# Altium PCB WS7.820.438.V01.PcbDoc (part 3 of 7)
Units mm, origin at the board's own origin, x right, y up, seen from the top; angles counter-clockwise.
Board outline 143.01 x 224 mm, 4 copper layers (Top Layer, G2, S3, Bottom Layer); 863 components, 638 nets, 2623 pads, 4664 vias.
Unrouted connection lines stored in the file: 16.
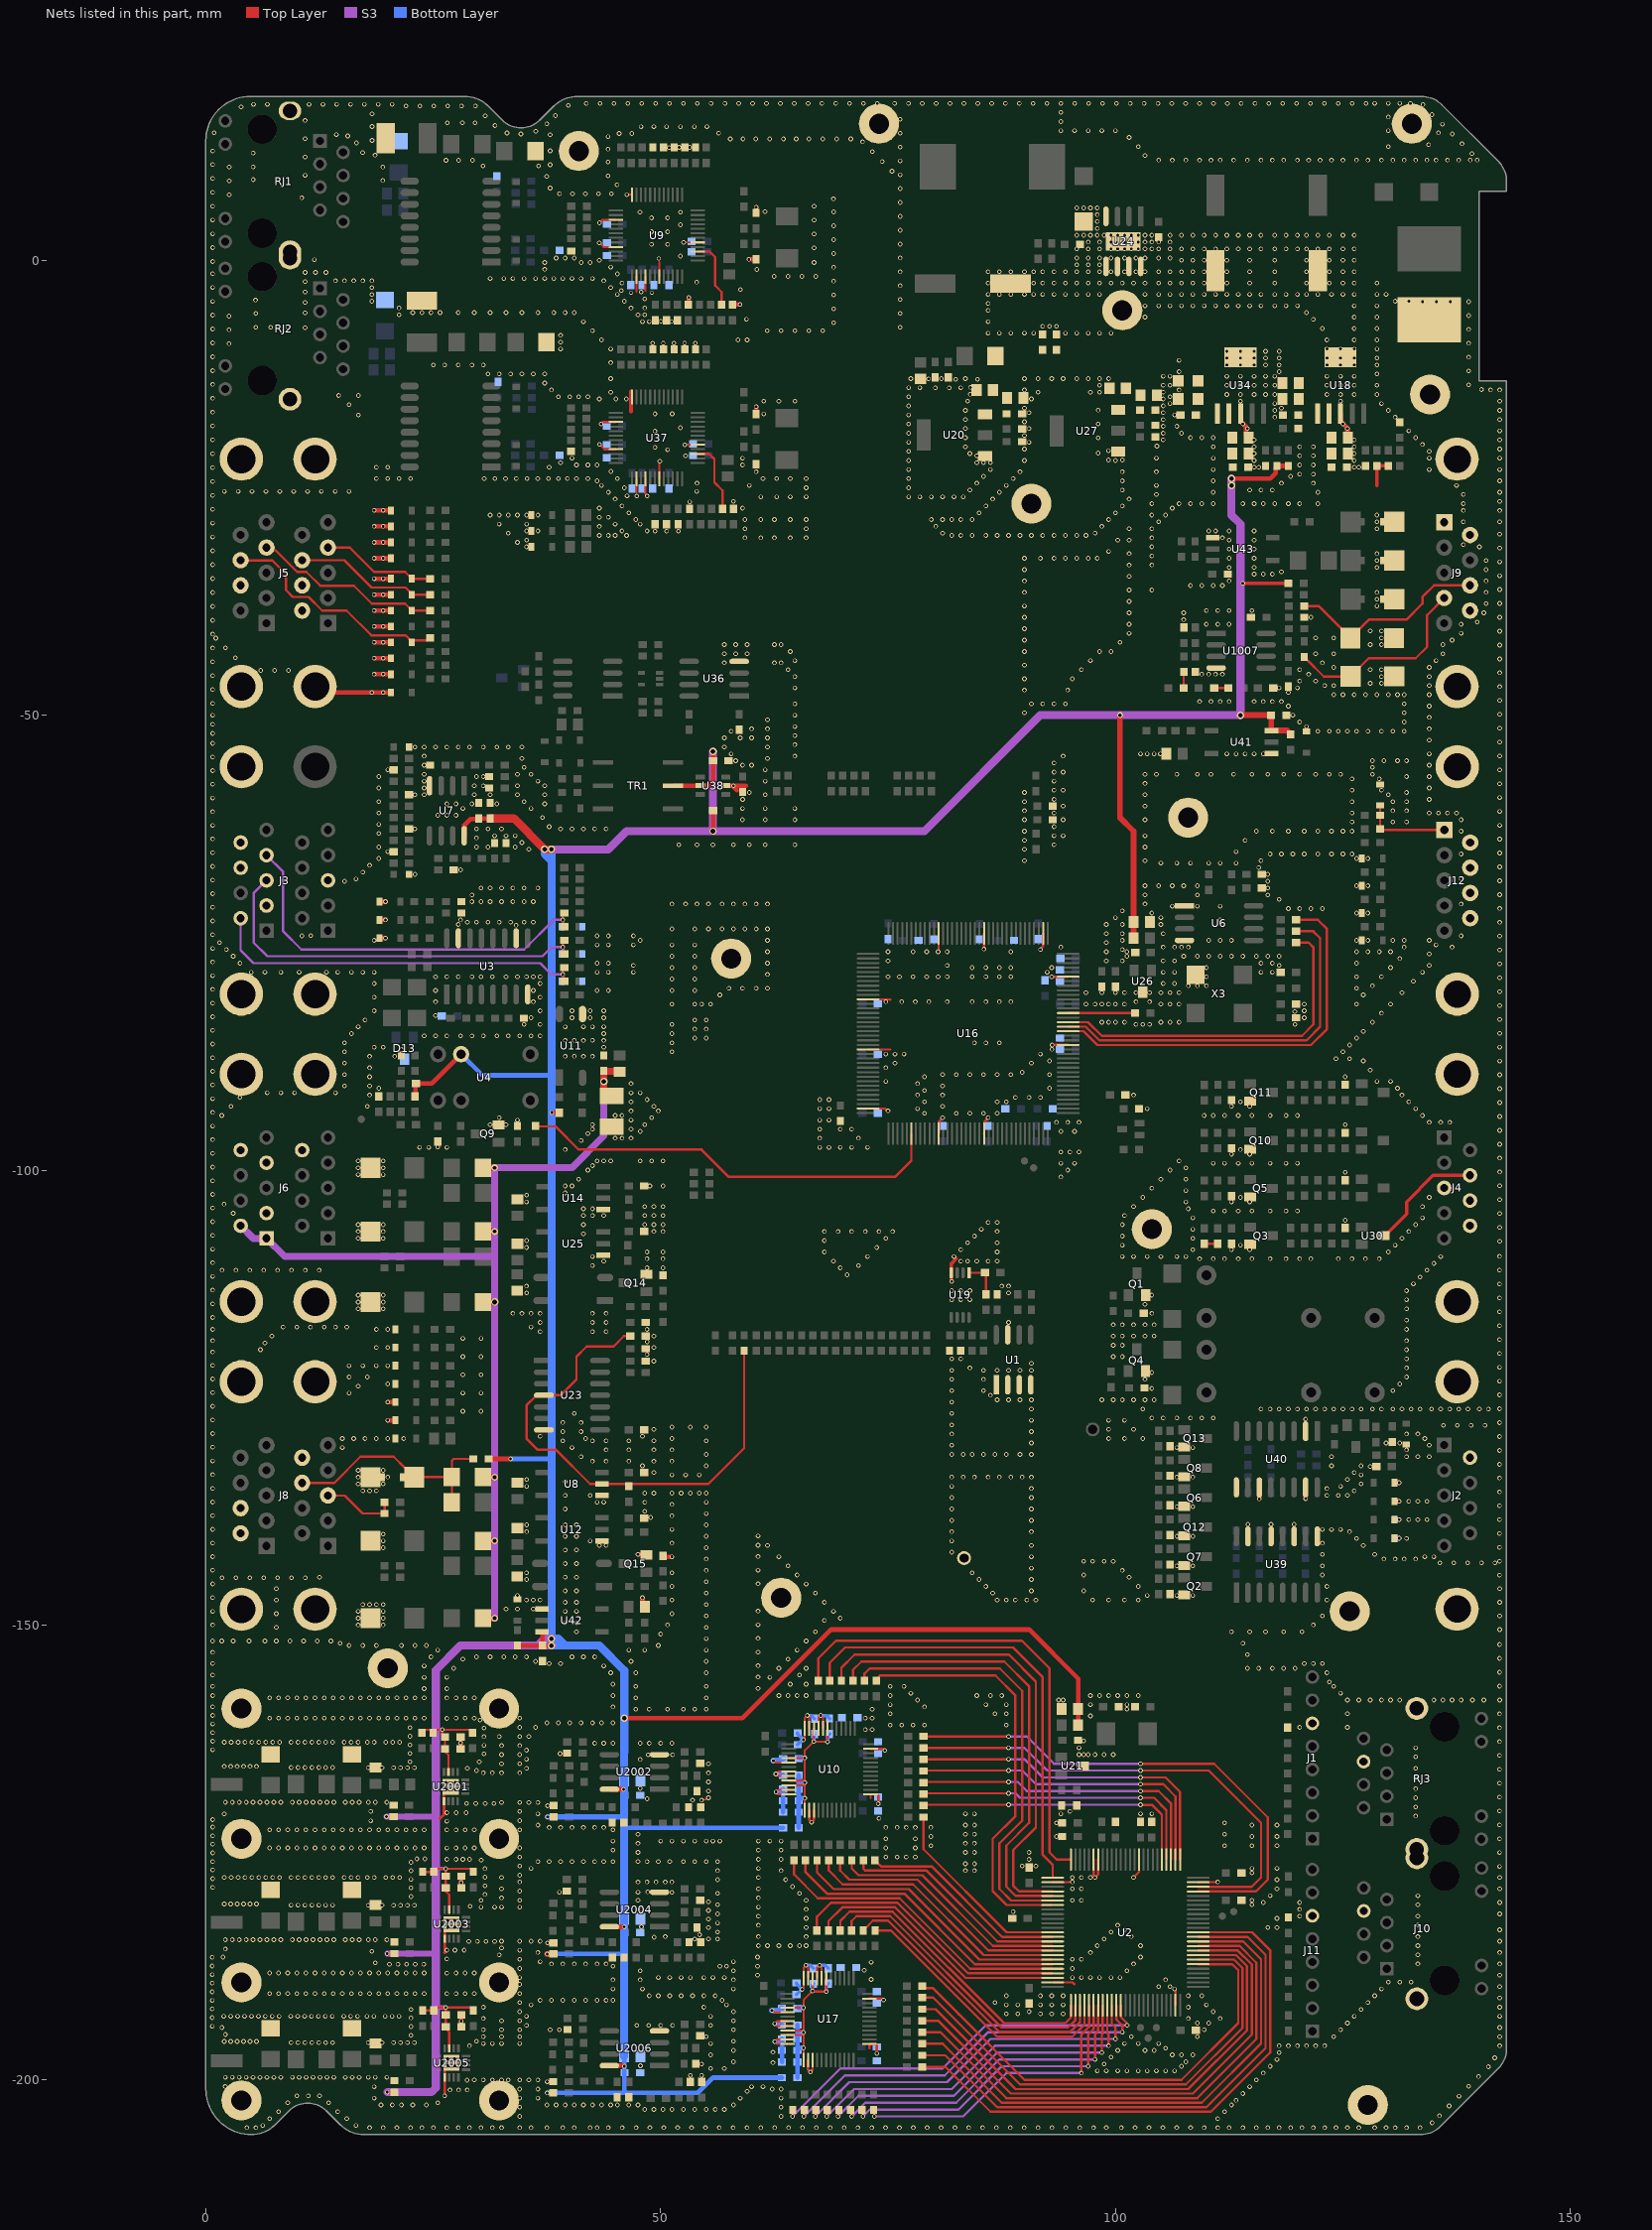
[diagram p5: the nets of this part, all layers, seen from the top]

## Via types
v1: diameter 0.508, hole 0.305, Top Layer to Bottom Layer, tented both sides, 4404 vias
v2: diameter 0.508, hole 0.3, Top Layer to Bottom Layer, tented both sides, 200 vias
v3: diameter 0.813, hole 0.508, Top Layer to Bottom Layer, tented both sides, 31 vias
v4: diameter 0.457, hole 0.305, Top Layer to Bottom Layer, tented both sides, 10 vias
v5: diameter 0.66, hole 0.406, Top Layer to Bottom Layer, tented both sides, 9 vias
v6: diameter 0.762, hole 0.406, Top Layer to Bottom Layer, tented both sides, 6 vias
v7: diameter 0.711, hole 0.406, Top Layer to Bottom Layer, tented both sides, 4 vias

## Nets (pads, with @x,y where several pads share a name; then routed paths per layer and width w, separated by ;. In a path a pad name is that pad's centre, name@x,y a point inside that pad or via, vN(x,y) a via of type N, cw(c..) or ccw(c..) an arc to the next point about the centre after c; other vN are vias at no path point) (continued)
24VIN_SHIDU: C80.2 C81.2 J6.A1 J6.A6 L1.2 R183.2 R189.2 R191.2 R193.2 R201.2 R227.2 | length 111
  Top Layer w0.762: R189.2@30.45,-114.5 v3(31.75,-114.5) ; R201.2@30.45,-106.75 v6(31.75,-106.75) ; R191.2@30.45,-99.75 v6(31.75,-99.75) ; R193.2@30.5,-149.25 v6(31.75,-149.25) ; R183.2@30.5,-140.75 v6(31.75,-140.75) ; R227.2@30.5,-133.75 v6(31.75,-133.75) ; C81.2@43.75,-89.1 C81.2@43.75,-89.136 ; C80.2@44.617,-91.837 44.269,-91.837 43.75,-91.318 v3(43.75,-90.25) C81.2@43.75,-89.136 ; L1.2@45.494,-89.21 45.439,-89.155 43.769,-89.155 C81.2@43.75,-89.136
  S3 w0.762: J6.A6@3.826,-106.118 5.211,-107.503 J6.A1@6.666,-107.503 8.663,-109.5 31.75,-109.5 ; v6(31.75,-149.25) v6(31.75,-140.75) v6(31.75,-133.75) v3(31.75,-114.5) 31.75,-109.5 ; v3(43.75,-90.25) 43.75,-96.25 40.25,-99.75 v6(31.75,-99.75) v6(31.75,-106.75) 31.75,-109.5
28V_SW: R226.1 U16.114 | length 47.3
  Top Layer w0.254: R226.1@36.25,-95.2 38.45,-95.2 41,-97.75 54.5,-97.75 57.5,-100.75 75.75,-100.75 77.551,-98.949 U16.114@77.551,-95.987
+5.5V: C28.2 C30.2 C87.2 C88.2 C90.2 C128.2 C129.2 C130.2 C178.2 C180.2 C181.2 C201.2 C202.2 C203.2 FB12.2 R160.2 U18.1 U20.3 U27.3 U34.1
+5V: C21.2 C22.1 C95.2 C112.2 C116.2 C124.2 C125.2 C175.2 C204.2 C205.2 C207.2 C2001.2 C2002.1 C2003.2 C2004.2 C2005.1 C2006.1 C2007.1 C2015.2 C2016.1 C2017.2 C2018.2 C2019.1 C2020.1 C2021.1 C2029.2 C2030.1 C2031.2 C2032.2 C2033.1 C2034.1 C2035.1 FB13.2 FB26.2 L2.1 L12.1 R15.1 R22.1 R46.2 R53.2 R58.1 R144.2 R159.2 R303.1 R352.1 R2005.2 R2015.1 R2020.2 R2035.1 R2041.2 R2054.1 TR1.2 U4.9 U7.8 U34.2 U38.5 U41.6 U42.6 U2001.15 U2002.8 U2003.15 U2004.8 U2005.15 U2006.8 | length 605.8
  Top Layer w0.254: v1(19.858,-171.072) R2015.1@20.634,-171.072 ; v1(19.946,-201.35) R2054.1@20.721,-201.35 ; v1(19.946,-186.11) R2035.1@20.721,-186.11 ; C2007.1@23.744,-161.84 24.063,-161.522 24.989,-161.522 24.994,-161.517 25.983,-161.517 v1(26,-161.5) ; C2035.1@23.832,-192.372 C2032.2@25.077,-192.372 25.42,-192.028 v1(26.372,-192.028) 29.051,-192.028 C2031.2@29.395,-192.372 ; C2021.1@23.832,-177.132 C2018.2@25.077,-177.132 25.42,-176.788 v1(26.372,-176.788) 29.051,-176.788 C2017.2@29.395,-177.132 ; v1@26.386,-192.042 C2029.2@26.386,-192.841 C2030.1@26.386,-194.145 26.386,-194.386 26.757,-194.757 U2005.15@26.757,-196.524 ; v1@26.386,-176.802 C2015.2@26.386,-177.601 C2016.1@26.386,-178.905 26.386,-179.273 26.757,-179.644 U2003.15@26.757,-181.284 ; U2001.15@26.624,-166.124 U2001.15@26.669,-166.169 26.669,-164.277 26.298,-163.906 C2002.1@26.298,-163.613 C2001.2@26.298,-162.309 26.273,-162.309 26,-162.036 v1(26,-161.5) ; C2003.2@29.307,-161.84 29.307,-161.79 29.034,-161.517 26.017,-161.517 v1(26,-161.5)
  Top Layer w0.381: v1(114,-35.5) R352.1@118.95,-35.5
  Top Layer w0.508: R144.2@23,-92 23.05,-91.95 23.05,-90.55 R53.2@23.1,-90.5 ; R53.2@23,-90.5 R53.2@23.1,-90.5 ; U4.9@28.065,-87.261 24.826,-90.5 R53.2@23.1,-90.5 ; U7.8@28.405,-63.25 28.423,-63.232 28.423,-62.077 29.1,-61.4 C21.2@30,-61.4 ; C21.2@30,-61.35 31.15,-61.35 C22.1@31.25,-61.25 ; R46.2@31.1,-131.75 v1(33.5,-131.75) ; R58.1@34.258,-152.258 C125.2@37,-152.258 ; U42.6@36.95,-150.77 36.954,-150.77 37,-150.816 C125.2@37,-152.258 ; v3(38,-152.258) C125.2@37,-152.258 ; v1(38.036,-93.687) R22.1@38.871,-93.687 R22.1@38.859,-93.675 ; U2006.8@44.367,-198.429 45.929,-198.429 v1(46,-198.5) ; U2004.8@44.367,-183.169 44.494,-183.169 v1@45.91,-183.169 ; U2002.8@44.367,-168.059 v1(45.91,-168.059) ; v3(46,-160.25) 59,-160.25 68.75,-150.5 90.5,-150.5 95.9,-155.9 C116.2@95.9,-158.75 ; TR1.2@51.357,-57.75 U38.5@54.357,-57.75 55.25,-57.75 55.757,-57.243 C112.2@55.757,-55 55.754,-54.996 55.754,-54.004 v3(55.75,-54) ; v3(55.75,-62.75) 55.754,-62.746 55.754,-60.503 R303.1@55.757,-60.5 ; L2.1@95.9,-161 C116.2@95.9,-159.25 ; v3(112.75,-24) 117,-24 117.619,-23.381 117.619,-22.731 R159.2@117.75,-22.6 C207.2@119,-22.6
  Top Layer w0.635: v1(37.526,-186.16) R2020.2@38.219,-186.16 ; v5(100.5,-50) 100.5,-61.25 102,-62.75 C175.2@102,-72.75 L12.1@102,-74.5 ; v3(113.75,-50) C124.2@117.1,-50 117.125,-50.025 117.125,-51.672 117.142,-51.69 U41.6@117.15,-51.69 118.88,-51.69 119.25,-52.06 R15.1@119.25,-52.11
  Top Layer w0.889: C22.1@31.25,-61.35 33.85,-61.35 v3(37.25,-64.75) v3(38,-64.75)
  S3 w0.254: 25.28,-161.517 25.983,-161.517 v1(26,-161.5)
  S3 w0.381: 25.28,-176.788 v1(26.372,-176.788)
  S3 w0.508: 25.381,-192.028 v1(26.372,-192.028)
  S3 w0.635: v1(19.858,-171.072) 25.192,-171.072 ; v1(19.946,-186.11) 25.242,-186.11
  S3 w0.889: v1(19.946,-201.35) 24.797,-201.35 25.28,-200.867 25.28,-176.788 25.28,-161.517 25.28,-154.97 28,-152.25 36.5,-152.25 37.25,-151.5 v3(38,-151.5) ; 36.5,-152.258 v3(38,-152.258) ; v3(37.25,-64.75) 44.25,-64.75 46.25,-62.75 v3(55.75,-62.75) ; v3(55.75,-54) v3(55.75,-62.75) ; v3(112.75,-24) v3(112.75,-24.75) 112.75,-28 113.75,-29 v3(113.75,-50) v5(100.5,-50) 91.75,-50 79,-62.75 v3(55.75,-62.75)
  Bottom Layer w0.508: U4.9@28.065,-87.261 30.39,-89.585 38,-89.585 ; v1(33.5,-131.75) 38,-131.75 ; v1(37.52,-201.434) 46.042,-201.434 ; v1(37.526,-186.16) 45.899,-186.16 ; C2034.1@45.992,-197.421 46,-197.429 v1(46,-198.5) 46,-201.392 46.042,-201.434 ; 45.992,-172.25 46.039,-172.296 FB26.2@63.472,-172.296 ; FB13.2@63.332,-199.746 55.754,-199.746 54.066,-201.434 46.042,-201.434
  Bottom Layer w0.635: v1(37.571,-171.089) 45.903,-171.089 45.992,-171
  Bottom Layer w0.889: v1@38,-93.723 38,-131.75 v3(38,-151.5) ; v1@38,-93.651 38,-89.585 38,-66.5 38,-66 ; 39.5,-152.25 38.75,-151.5 v3(38,-151.5) ; C2034.1@45.992,-197.421 C2020.1@45.992,-182.288 45.992,-172.25 45.992,-171 C2006.1@45.992,-167.068 45.992,-163.935 46,-163.927 v3(46,-160.25) 46,-155 43.258,-152.258 v3(38,-152.258) v3(38,-151.5) ; 38,-66 37.25,-65.25 v3(37.25,-64.75) v3(38,-64.75) 38,-66
  other v1: 45.992,-183.177
+5V_1: C131.2 C132.2 C133.2 C134.2 J9.1 R108.2 U18.2 | length 3.4
  Top Layer w0.381: 128.75,-24.75 C131.2@128.75,-22.6 R108.2@130,-22.6
+5VA1: C73.2 C74.2 C75.2 C76.2 C77.2 C78.2 C79.2 FB13.1 U17.4 U17.9 U17.10 U17.13 U17.43 U17.46 | length 27.4
  Top Layer w0.229: U17.10@63.954,-195.059 65.702,-195.059 ; U17.9@63.954,-194.559 v1@65.699,-194.559 ; U17.4@63.954,-192.059 v1@65.699,-192.059 ; U17.13@65.704,-197.809 v1@65.704,-196.51 ; v1(65.704,-196.484) v1(65.704,-194.782) v1(65.704,-192.065) 65.704,-191.231 v1(66.692,-190.244) 66.692,-188.822 U17.46@66.704,-188.809 ; v1@66.692,-190.293 v1@68.203,-190.293 ; v1(68.204,-190.292) U17.43@68.204,-188.809
  Bottom Layer w0.381: v1(66.692,-190.244) 66.692,-189.512 C77.2@66.775,-189.429 ; v1(68.204,-190.292) 68.204,-189.65 C78.2@68.426,-189.429
  Bottom Layer w0.508: FB13.1@65.032,-199.746 C79.2@65.032,-198.032 C76.2@65.032,-196.762 ; C74.2@65.032,-193.968 65.032,-194.782 ; C73.2@65.032,-192.003 65.094,-192.065 v1(65.704,-192.065) ; v1(65.704,-196.484) 65.31,-196.484 C76.2@65.032,-196.762 ; v1(65.704,-194.782) 65.032,-194.782 ; C76.2@65.032,-196.762 C75.2@65.032,-195.492 65.032,-194.782
+5VA2: C91.2 C92.2 C96.2 C97.2 C98.2 C99.2 C100.2 FB26.1 U10.4 U10.9 U10.10 U10.13 U10.43 U10.46 | length 27.4
  Top Layer w0.229: U10.10@64.094,-167.609 65.842,-167.609 ; U10.9@64.094,-167.109 v1@65.839,-167.109 ; U10.4@64.094,-164.609 v1@65.839,-164.609 ; U10.13@65.844,-170.359 v1@65.844,-169.06 ; v1(65.844,-169.034) v1(65.844,-167.332) v1(65.844,-164.615) 65.844,-163.781 v1(66.832,-162.794) 66.832,-161.372 U10.46@66.844,-161.359 ; v1@66.832,-162.843 v1@68.343,-162.843 ; v1(68.344,-162.842) U10.43@68.344,-161.359
  Bottom Layer w0.381: v1(66.832,-162.794) 66.832,-162.062 C98.2@66.915,-161.979 ; v1(68.344,-162.842) 68.344,-162.2 C99.2@68.566,-161.979
  Bottom Layer w0.508: FB26.1@65.172,-172.296 C100.2@65.172,-170.582 C97.2@65.172,-169.312 ; C92.2@65.172,-166.518 65.172,-167.332 ; C91.2@65.172,-164.553 65.234,-164.615 v1(65.844,-164.615) ; v1(65.844,-169.034) 65.451,-169.034 C97.2@65.172,-169.312 ; v1(65.844,-167.332) 65.172,-167.332 ; C97.2@65.172,-169.312 C96.2@65.172,-168.042 65.172,-167.332
ACTLED: R73.2 U9.27 | length 7.7
  Top Layer w0.254: U9.27@54.092,0.963 55.374,0.963 56,0.337 56,-2.792 56.692,-3.484 R73.2@56.692,-4.895
ACTLED2: R275.2 U37.27 | length 7.9
  Top Layer w0.254: U37.27@54.092,-21.275 55.337,-21.275 55.899,-21.837 55.899,-24.399 56.802,-25.302 56.802,-26.843 R275.2@56.802,-27.311
AD1_BUSY: R117.2 U2.54 | length 30.6
  Top Layer w0.254: R117.2@73.576,-183.579 75.329,-183.579 87,-195.25 95.25,-195.25 96.596,-193.904 U2.54@96.596,-191.781 ; R117.2@73.849,-183.256 R117.2@73.877,-183.256
AD1_BYTE: R112.2 U2.52 | length 32.9
  Top Layer w0.254: R112.2@70.994,-183.569 70.994,-182.54 71.534,-182 75.25,-182 87.5,-194.25 94.772,-194.25 95.596,-193.426 U2.52@95.596,-191.781
AD1_CONVST: R99.2 U2.51 | length 33.5
  Top Layer w0.254: R99.2@69.724,-183.569 69.75,-183.544 69.75,-182.514 70.764,-181.5 75.5,-181.5 87.75,-193.75 94.5,-193.75 95.096,-193.154 U2.51@95.096,-191.781
AD1_CS: R48.2 U2.47 | length 31.3
  Top Layer w0.254: R48.2@67.184,-183.569 67.184,-182.066 68.719,-180.531 76.031,-180.531 83.781,-188.281 U2.47@93.096,-188.281
AD1_D0: R118.2 U2.81 | length 52.1
  Top Layer w0.254: R118.2@78.755,-189.682 78.966,-189.894 79.894,-189.894 82.784,-192.784 90,-200 107.25,-200 113.5,-193.75 113.5,-187.95 112.832,-187.281 U2.81@109.096,-187.281
AD1_D1: R122.2 U2.82 | length 53.6
  Top Layer w0.254: R122.2@78.755,-190.952 79.952,-190.952 89.5,-200.5 107.75,-200.5 113.967,-194.283 113.967,-187.709 113.039,-186.781 U2.82@109.096,-186.781
AD1_D2: R124.2 U2.83 | length 54.9
  Top Layer w0.254: R124.2@78.755,-192.222 80.222,-192.222 89,-201 108,-201 114.467,-194.533 114.467,-187.502 113.246,-186.281 U2.83@109.096,-186.281
AD1_D3: R125.2 U2.84 | length 56.5
  Top Layer w0.254: R125.2@78.755,-193.492 80.492,-193.492 88.5,-201.5 108.5,-201.5 115,-195 115,-187.328 113.453,-185.781 U2.84@109.096,-185.781
AD1_D4: R126.2 U2.85 | length 58
  Top Layer w0.254: R126.2@78.755,-194.762 80.762,-194.762 88,-202 109,-202 115.5,-195.5 115.5,-187.121 113.66,-185.281 U2.85@109.096,-185.281
AD1_D5: R130.2 U2.86 | length 59.6
  Top Layer w0.254: R130.2@78.755,-196.032 81.032,-196.032 87.5,-202.5 109.5,-202.5 116,-196 116,-186.75 114.031,-184.781 U2.86@109.096,-184.781
AD1_D6: R131.2 U2.87 | length 61.3
  Top Layer w0.254: R131.2@78.755,-197.302 81.302,-197.302 87,-203 110,-203 116.5,-196.5 116.5,-186.25 114.531,-184.281 U2.87@109.096,-184.281
AD1_D7: R132.2 U2.88 | length 62.9
  Top Layer w0.254: R132.2@78.755,-198.572 81.322,-198.572 86.25,-203.5 110.5,-203.5 117,-197 117,-185.75 115.031,-183.781 U2.88@109.096,-183.781
AD1_D8: R140.1 U2.55 | length 32.5
  Top Layer w0.254: v1(96.25,-199.25) 96.25,-195 97.096,-194.154 U2.55@97.096,-191.781
  S3 w0.254: v1(73.5,-204) 83.25,-204 88,-199.25 v1(96.25,-199.25)
AD1_D9: R139.1 U2.56 | length 34
  Top Layer w0.254: v1(97,-198.5) 97,-195 97.596,-194.404 U2.56@97.596,-191.781
  S3 w0.254: v1(72.25,-204) 72.976,-203.274 82.726,-203.274 87.5,-198.5 v1(97,-198.5)
AD1_D10: R138.1 U2.57 | length 35.5
  Top Layer w0.254: v1(97.75,-197.75) 97.75,-195 98.096,-194.654 U2.57@98.096,-191.781
  S3 w0.254: v1(71,-204) 72.5,-202.5 82.5,-202.5 87.25,-197.75 v1(97.75,-197.75)
AD1_D11: R137.1 U2.58 | length 37.2
  Top Layer w0.254: v1(98.5,-197) 98.5,-195 98.596,-194.904 U2.58@98.596,-191.781
  S3 w0.254: v1(69.5,-204) 71.75,-201.75 82.25,-201.75 87,-197 v1(98.5,-197)
AD1_D12: R136.1 U2.59 | length 38.7
  Top Layer w0.254: U2.59@99.096,-191.781 99.096,-194.846 99.25,-195 v1(99.25,-196.25)
  S3 w0.254: v1(68.25,-204) 71.25,-201 82,-201 86.75,-196.25 v1(99.25,-196.25)
AD1_D13: R135.1 U2.60 | length 40.4
  Top Layer w0.254: U2.60@99.596,-191.781 99.596,-193.846 100,-194.25 v1(100,-195.5)
  S3 w0.254: v1(67,-204) 70.75,-200.25 81.5,-200.25 86.25,-195.5 v1(100,-195.5)
AD1_D14: R134.1 U2.61 | length 42.1
  Top Layer w0.254: U2.61@100.096,-191.781 100.096,-193.346 100.75,-194 v1(100.75,-194.75)
  S3 w0.254: v1(65.75,-204) 70.25,-199.5 81.25,-199.5 86,-194.75 v1(100.75,-194.75)
AD1_D15: R133.1 U2.62 | length 43.4
  Top Layer w0.254: U2.62@100.596,-191.781 100.596,-193.096 101.235,-193.735 101.235,-193.951 v1(101.283,-194)
  S3 w0.254: v1(64.5,-204) 69.75,-198.75 81,-198.75 85.75,-194 v1(101.283,-194)
AD1_RD: R60.2 U2.48 | length 29.5
  Top Layer w0.254: R60.2@68.454,-183.569 68.454,-182.546 69.969,-181.031 75.781,-181.031 83.531,-188.781 U2.48@93.096,-188.781
AD1_RESET: R114.2 U2.53 | length 31.7
  Top Layer w0.254: R114.2@72.264,-183.569 72.264,-183.519 72.537,-183.246 72.587,-183.246 73.334,-182.5 75,-182.5 87.25,-194.75 95,-194.75 96.096,-193.654 U2.53@96.096,-191.781
AD2_BUSY: R237.2 U2.32 | length 46.2
  Top Layer w0.254: R237.2@73.639,-156.007 74.104,-155.542 86.792,-155.542 89,-157.75 89,-171 86.5,-173.5 86.5,-179.25 88.031,-180.781 U2.32@93.096,-180.781
AD2_BYTE: R235.2 U2.30 | length 50.6
  Top Layer w0.254: R235.2@71.134,-156.119 71.134,-154.956 72.072,-154.018 87.792,-154.018 90.5,-156.726 90.5,-171.75 88,-174.25 88,-178.75 89.031,-179.781 U2.30@93.096,-179.781
AD2_CONVST: R234.2 U2.29 | length 52.7
  Top Layer w0.254: R234.2@69.864,-156.119 69.864,-154.702 71.309,-153.257 88.292,-153.257 91.25,-156.215 91.25,-172.25 88.75,-174.75 88.75,-178.633 89.399,-179.281 U2.29@93.096,-179.281
AD2_CS: R232.2 U2.25 | length 52.8
  Top Layer w0.254: R232.2@67.324,-156.119 67.324,-153.676 69.274,-151.726 89.726,-151.726 92.75,-154.75 92.75,-175 93.531,-175.781 U2.25@95.096,-175.781
AD2_D0: R238.2 U2.97 | length 56.6
  Top Layer w0.254: R238.2@78.895,-162.232 78.913,-162.25 v1(88.25,-162.25) ; v1(102.75,-165.25) 110.85,-165.25 116.75,-171.15 116.75,-178 115.469,-179.281 U2.97@109.096,-179.281
  S3 w0.254: v1(88.25,-162.25) 90.25,-162.25 93.25,-165.25 v1(102.75,-165.25)
AD2_D1: R239.2 U2.98 | length 53.9
  Top Layer w0.254: R239.2@78.896,-163.5 v1(88.25,-163.5) ; v1(102.75,-166) 110.25,-166 116,-171.75 116,-175.25 116,-177.75 114.967,-178.783 U2.98@109.096,-178.781 U2.98@109.096,-178.781
  S3 w0.254: v1(88.25,-163.5) 90,-163.5 92.5,-166 v1(102.75,-166)
AD2_D2: R240.2 U2.1 | length 37.1
  Top Layer w0.254: R240.2@78.895,-164.772 78.916,-164.75 v1(88.25,-164.75) ; v1(102.75,-166.75) 105.5,-166.75 107.096,-168.346 U2.1@107.096,-175.781
  S3 w0.254: v1(88.25,-164.75) 90,-164.75 92,-166.75 v1(102.75,-166.75)
AD2_D3: R241.2 U2.2 | length 35.8
  Top Layer w0.254: R241.2@78.895,-166.042 78.936,-166 v1(88.25,-166) ; v1(102.75,-167.5) 105.25,-167.5 106.596,-168.846 U2.2@106.596,-175.781
  S3 w0.254: v1(88.25,-166) 89.75,-166 91.25,-167.5 v1(102.75,-167.5)
AD2_D4: R242.2 U2.3 | length 34.4
  Top Layer w0.254: R242.2@78.895,-167.312 78.956,-167.25 v1(88.25,-167.25) ; v1(102.75,-168.25) 104.75,-168.25 106.096,-169.596 U2.3@106.096,-175.781
  S3 w0.254: v1(88.25,-167.25) 89.25,-167.25 90.25,-168.25 v1(102.75,-168.25)
AD2_D5: R243.2 U2.4 | length 32.9
  Top Layer w0.254: R243.2@78.895,-168.582 78.976,-168.5 v1(88.25,-168.5) ; v1(102.75,-169) 104.25,-169 105.596,-170.346 U2.4@105.596,-175.781
  S3 w0.254: v1(88.25,-168.5) 89,-168.5 89.5,-169 v1(102.75,-169)
AD2_D6: R244.2 U2.5 | length 31.6
  Top Layer w0.254: R244.2@78.895,-169.852 78.996,-169.75 v1(88.25,-169.75) ; v1(102.75,-169.75) 102.799,-169.799 104.049,-169.799 105.096,-170.846 U2.5@105.096,-175.781
  S3 w0.254: v1(88.25,-169.75) v1(102.75,-169.75)
AD2_D7: R245.2 U2.38 | length 21.5
  Top Layer w0.254: R245.2@78.895,-171.122 78.895,-174.645 88.031,-183.781 U2.38@93.096,-183.781
AD2_D8: R253.1 U2.39 | length 23.1
  Top Layer w0.254: R253.1@73.547,-175.853 73.547,-175.903 73.82,-176.176 73.87,-176.176 74.226,-176.531 79.781,-176.531 87.531,-184.281 U2.39@93.096,-184.281
AD2_D9: R252.1 U2.40 | length 25.1
  Top Layer w0.254: R252.1@72.277,-175.853 72.286,-175.861 72.286,-176.786 72.5,-177 79.25,-177 87.031,-184.781 U2.40@93.096,-184.781
AD2_D10: R251.1 U2.41 | length 26.5
  Top Layer w0.254: R251.1@71.007,-175.853 71.007,-176.757 71.75,-177.5 78.75,-177.5 86.531,-185.281 U2.41@93.096,-185.281
AD2_D11: R250.1 U2.42 | length 28.1
  Top Layer w0.254: R250.1@69.737,-175.853 69.737,-176.987 70.75,-178 78.25,-178 86.031,-185.781 U2.42@93.096,-185.781
AD2_D12: R249.1 U2.43 | length 29.6
  Top Layer w0.254: R249.1@68.467,-175.853 68.467,-176.967 70,-178.5 77.75,-178.5 85.531,-186.281 U2.43@93.096,-186.281
AD2_D13: R248.1 U2.44 | length 31.2
  Top Layer w0.254: R248.1@67.197,-175.853 67.197,-177.197 69.031,-179.031 77.281,-179.031 85.031,-186.781 U2.44@93.096,-186.781
AD2_D14: R247.1 U2.45 | length 32.7
  Top Layer w0.254: R247.1@65.927,-175.853 65.927,-177.177 68.281,-179.531 76.781,-179.531 84.531,-187.281 U2.45@93.096,-187.281
AD2_D15: R246.1 U2.46 | length 34.3
  Top Layer w0.254: R246.1@64.657,-175.853 64.657,-177.407 67.281,-180.031 76.281,-180.031 84.031,-187.781 U2.46@93.096,-187.781
AD2_RD: R233.2 U2.26 | length 49.9
  Top Layer w0.254: R233.2@68.594,-156.119 68.594,-154.156 70.274,-152.476 88.726,-152.476 92,-155.75 92,-175.25 93.096,-176.346 U2.26@93.096,-177.781
AD2_RESET: R236.2 U2.31 | length 48.5
  Top Layer w0.254: R236.2@72.404,-156.119 72.404,-155.346 72.97,-154.78 87.292,-154.78 89.75,-157.238 89.75,-171.5 87.25,-174 87.25,-179 88.531,-180.281 U2.31@93.096,-180.281
AGND1: C52.2 C53.2 C73.1 C74.1 C75.1 C76.1 C77.1 C78.1 C79.1 FB15.2 U17.5 U17.7 U17.8 U17.11 U17.12 U17.14 U17.15 U17.44 U17.45 U17.47 U17.48 | length 27.4
  Top Layer w0.229: v1(62.242,-192.369) 62.432,-192.559 U17.5@63.954,-192.559 ; U17.12@63.954,-196.059 62.808,-196.059 v1(62.547,-195.798) 62.786,-195.559 U17.11@63.954,-195.559 ; U17.8@63.954,-194.059 62.764,-194.059 v1(62.522,-193.817) 62.78,-193.559 U17.7@63.954,-193.559 ; v1@65.704,-189.897 U17.48@65.704,-188.809 65.704,-187.663 v1(65.976,-187.391) 66.204,-187.619 U17.47@66.204,-188.809 ; U17.45@67.204,-188.809 67.204,-187.661 v1(67.475,-187.391) 67.704,-187.621 U17.44@67.704,-188.809
  Top Layer w0.254: U17.14@66.204,-197.809 66.204,-198.872 v1(66.459,-199.126) 66.704,-198.88 U17.15@66.704,-197.809
  Bottom Layer w0.381: C53.2@64.922,-190.606 65.472,-190.056 v1(65.545,-190.056) ; C52.2@64.922,-189.336 64.922,-189.433 v1(65.545,-190.056) ; v1@65.545,-189.959 v1(65.545,-190.056) ; v1(65.976,-187.391) 66.437,-187.391 C77.1@66.775,-187.729 ; v1(67.475,-187.391) 68.088,-187.391 C78.1@68.426,-187.729
  Bottom Layer w0.508: v1(62.522,-193.817) 63.181,-193.817 C74.1@63.332,-193.968 ; v1(62.547,-195.798) 63.026,-195.798 C75.1@63.332,-195.492 C76.1@63.332,-196.762 C79.1@63.332,-198.032
  Bottom Layer w0.635: v1(62.242,-192.369) 63.093,-192.369 C73.1@63.332,-192.13
  other v1: 62.344,-198.105 62.344,-196.962
AGND2: C63.2 C64.2 C91.1 C92.1 C96.1 C97.1 C98.1 C99.1 C100.1 FB28.2 U10.5 U10.7 U10.8 U10.11 U10.12 U10.14 U10.15 U10.44 U10.45 U10.47 U10.48 | length 27.4
  Top Layer w0.229: v1(62.382,-164.919) 62.572,-165.109 U10.5@64.094,-165.109 ; U10.12@64.094,-168.609 62.948,-168.609 v1(62.687,-168.348) 62.926,-168.109 U10.11@64.094,-168.109 ; U10.8@64.094,-166.609 62.904,-166.609 v1(62.662,-166.367) 62.92,-166.109 U10.7@64.094,-166.109 ; v1@65.844,-162.447 U10.48@65.844,-161.359 65.844,-160.213 v1(66.116,-159.941) 66.344,-160.169 U10.47@66.344,-161.359 ; U10.45@67.344,-161.359 67.344,-160.211 v1(67.615,-159.941) 67.844,-160.171 U10.44@67.844,-161.359
  Top Layer w0.254: U10.14@66.344,-170.359 66.344,-171.422 v1(66.599,-171.676) 66.844,-171.43 U10.15@66.844,-170.359
  Bottom Layer w0.381: C64.2@65.062,-163.156 65.612,-162.606 v1(65.685,-162.606) ; C63.2@65.062,-161.886 65.062,-161.983 v1(65.685,-162.606) ; v1@65.685,-162.509 v1(65.685,-162.606) ; v1(66.116,-159.941) 66.577,-159.941 C98.1@66.915,-160.279 ; v1(67.615,-159.941) 68.228,-159.941 C99.1@68.566,-160.279
  Bottom Layer w0.508: v1(62.662,-166.367) 63.321,-166.367 C92.1@63.472,-166.518 ; v1(62.687,-168.348) 63.166,-168.348 C96.1@63.472,-168.042 C97.1@63.472,-169.312 C100.1@63.472,-170.582
  Bottom Layer w0.635: v1(62.382,-164.919) 63.233,-164.919 C91.1@63.472,-164.68
BAP70Q_Vctrl_1: D66.2 J9.4 R351.2 | length 21.9
  Top Layer w0.254: R351.2@120.75,-43.6 120.75,-43.65 121.023,-43.923 121.073,-43.923 122.9,-45.75 D66.2@125.85,-45.75 127.85,-43.75 133,-43.75 134.25,-42.5 134.25,-39.009 J9.4@136.139,-37.121
BAP70Q_Vctrl_2: D67.2 J9.8 R350.2 | length 22.6
  Top Layer w0.254: R350.2@120.75,-38 122.33,-38 125.815,-41.485 D67.2@125.815,-41.535 127.85,-39.5 132,-39.5 133.75,-37.75 133.75,-37 135.014,-35.736 J9.8@138.979,-35.736
BD_TEMP: R172.1 R209.2 U19.1 | length 4.5
  Top Layer w0.254: U19.1@83.899,-111.292 85.858,-111.292 85.9,-111.25 R209.2@86,-111.35 ; R172.1@85.75,-113.65 R209.2@85.75,-111.35
BD_TEMP_HCQ: D35.1 J3.A6 R121.2 R127.2 | length 42.5
  Top Layer w0.254: R127.2@39.4,-79.25 39.25,-79.1 v1(39.25,-78.5) 39.25,-77.9 R121.2@39.4,-77.75
  S3 w0.254: J3.A6@3.826,-72.312 3.826,-75.826 5.25,-77.25 36.75,-77.25 38,-78.5 v1(39.25,-78.5)
  Bottom Layer w0.254: D35.1@39.25,-79.327 v1(39.25,-78.5)
BD_TEMP_JG1: D36.1 J3.A3 R120.2 R128.2 | length 44.8
  Top Layer w0.254: R128.2@39.4,-76.25 39.25,-76.1 v1(39.25,-75.5) 39.25,-74.9 R120.2@39.4,-74.75
  S3 w0.254: J3.A3@6.666,-68.157 5.25,-69.573 5.25,-75 6.75,-76.5 37,-76.5 38,-75.5 v1(39.25,-75.5)
  Bottom Layer w0.254: D36.1@39.25,-76.25 v1(39.25,-75.5)
BD_TEMP_JG2: D37.1 J3.A4 R17.2 R129.2 | length 44.4
  Top Layer w0.254: R129.2@39.4,-73.25 39.25,-73.1 v1(39.25,-72.5) 39.25,-71.9 R17.2@39.4,-71.75
  S3 w0.254: J3.A4@6.666,-65.387 8.5,-67.221 8.5,-73.75 10.5,-75.75 35,-75.75 38.25,-72.5 v1(39.25,-72.5)
  Bottom Layer w0.254: D37.1@39.25,-73.25 v1(39.25,-72.5)
BD_temp_PA: D74.1 J12.1 R322.1 R325.2 | length 9.7
  Top Layer w0.254: D74.1@129.1,-59.9 R322.1@129.1,-61 R325.2@129.1,-62.5 129.217,-62.617 J12.1@136.16,-62.617
buzzer_24V: J4.7 U30.3 | length 13
  Top Layer w0.381: U30.3@129.47,-107.21 129.62,-107.21 132,-104.83 132,-103.5 134.922,-100.578 J4.7@138.979,-100.578
buzzer_ctrl: R173.2 R260.1 | length 1.5
  Top Layer w0.254: R173.2@109.75,-108.1 R260.1@111.25,-108.1
COMM11_LED: D5.1 J5.A8 R167.1 | length 25.7
  Top Layer w0.254: J5.A8@3.826,-32.966 3.86,-33 7.3,-33 8.8,-34.5 8.8,-36.25 9.55,-37 11.3,-37 12.8,-38.5 15.469,-38.5 18.207,-41.238 21.988,-41.238 22.65,-41.9 22.777,-41.773 24.377,-41.773 R167.1@24.65,-41.5
COMM22_LED: D10.1 J5.B8 R171.1 | length 15.6
  Top Layer w0.254: J5.B8@10.586,-32.966 15.216,-32.966 18.216,-35.966 21.966,-35.966 22.75,-36.75 R171.1@24.65,-36.75
CPU_CLK: R92.2 U16.19 | length 44.6
  Top Layer w0.254: U16.19@94.801,-84.737 96.487,-84.737 98,-86.25 121.5,-86.25 123.25,-84.5 123.25,-73.5 122.25,-72.5 R92.2@119.85,-72.5
CPU_MISO: R91.1 U16.20 | length 41.7
  Top Layer w0.254: U16.20@94.801,-84.237 96.737,-84.237 98.25,-85.75 121,-85.75 122.5,-84.25 122.5,-74.5 121.75,-73.75 R91.1@119.85,-73.75
CPU_MOSI: R93.2 U16.21 | length 38.7
  Top Layer w0.254: U16.21@94.801,-83.737 96.987,-83.737 98.5,-85.25 120.5,-85.25 121.75,-84 121.75,-75.5 121.25,-75 R93.2@119.85,-75
CPU_USERCLK: R45.2 U16.23 | length 7.4
  Top Layer w0.254: U16.23@94.801,-82.737 102.137,-82.737 R45.2@102.15,-82.75
CURR11_LED: D4.1 J5.A4 R116.1 | length 20.9
  Top Layer w0.254: J5.A4@6.666,-31.581 6.96,-31.875 7.675,-31.875 10.05,-34.25 11.05,-34.25 12.587,-35.787 16.287,-35.787 18.25,-37.75 21.9,-37.75 D4.1@22.65,-38.5 R116.1@24.65,-38.5
CURR22_LED: D9.1 J5.B4 R170.1 | length 12.6
  Top Layer w0.254: J5.B4@13.426,-31.581 15.831,-31.581 18.5,-34.25 21.9,-34.25 D9.1@22.65,-35 R170.1@24.65,-35
DAC_Att1: R96.1 R1038.2 | length 1.5
  Top Layer w0.254: R96.1@110.85,-47 R1038.2@112.4,-47
DAC_Att2: R97.1 R1026.2 | length 1.8
  Top Layer w0.254: R97.1@107.5,-47 107.5,-45.257 R1026.2@107.515,-45.242
FASTLOCK: R202.2 R217.2 R221.2 U8.5 U23.4 | length 58.3
  Top Layer w0.254: R202.2@46.65,-118.25 45.961,-118.25 44.831,-119.38 41.87,-119.38 40.75,-120.5 40.75,-123 39,-124.75 36.364,-124.75 35.25,-125.864 35.25,-129.5 36.5,-130.75 38.5,-130.75 42.25,-134.5 U8.5@43.55,-134.5 46.5,-134.5 55.25,-134.5 59.182,-130.568 R221.2@59.182,-119.55
FASTLOCK+: D42.1 D59.2 J8.B8 R46.1 R50.2 R227.1 | length 25.6
  Top Layer w0.254: J8.B8@10.586,-134.384 14.116,-134.384 17,-131.5 20.65,-131.5 21.877,-132.727 21.927,-132.727 22.9,-133.7 D59.2@22.9,-133.75 R227.1@27.05,-133.75 ; R50.2@27.05,-136.5 R227.1@27.05,-133.75 ; R46.1@29.4,-131.75 27.25,-131.75 27.05,-131.95 R227.1@27.05,-133.75
FASTLOCK-: J8.B3 R57.2 R182.2 | length 8.3
  Top Layer w0.254: J8.B3@13.426,-135.769 15.269,-135.769 17.25,-137.75 R182.2@19.65,-137.75 R57.2@19.65,-136.5
GND: BT1.2 C1.1 C2.1 C3.1 C4.1 C5.1 C6.1 C7.1 C8.1 C9.1 C10.2 C11.1 C13.1 C14.2 C15.2 C17.2 C18.1 C21.1 C22.2 C23.1 C24.2 C25.1 C26.1 C27.1 C28.1 C29.1 C30.1 C31.1 C32.1 C33.1 C34.1 C35.1 C36.1 C37.1 C38.1 C39.1 C40.1 C41.1 C42.1 C43.1 C44.1 C45.1 C46.1 C47.2 C48.1 C49.1 C50.1 C51.1 C54.1 C55.1 C56.2 C57.2 C58.1 C59.1 C60.1 C61.2 C62.2 C65.1 C66.1 C67.1 C68.1 C69.1 C70.1 C71.1 C72.1 C80.1 C81.1 C82.2 C83.2 C84.1 C85.1 C86.1 C87.1 C88.1 C89.1 C90.1 C93.1 C94.2 C95.1 C101.1 C102.1 C103.1 C104.1 C105.1 C106.1 C107.1 C109.1 C112.1 C115.1 C116.1 C117.1 C118.1 C119.1 C120.1 C121.1 C122.1 C123.1 C124.1 C125.1 C126.1 C127.1 C128.1 C129.1 C130.1 C132.1 C133.1 C134.1 C138.1 C139.2 C140.2 C141.1 C142.1 C154.1 C155.1 C157.1 C158.1 C159.1 C160.1 C162.2 C163.1 C164.2 C169.1 C171.1 C172.1 C173.1 C174.1 C175.1 C176.1 C177.1 C178.1 C179.1 C180.1 C181.1 C201.1 C202.1 C203.1 C204.1 C205.1 C225.1 C226.1 C227.1 C228.1 C229.1 C230.1 C231.1 C232.1 C233.1 C234.1 C235.1 C236.1 C237.1 C238.1 C239.1 C240.1 C241.2 C242.1 C243.1 C1053.1 C1054.2 C1061.1 C1068.1 C2001.1 C2002.2 C2005.2 C2006.2 C2009.1 C2010.1 C2011.1 C2012.1 C2013.1 C2014.1 C2015.1 C2016.2 C2019.2 C2020.2 C2023.1 C2024.1 C2025.1 C2026.1 C2027.1 C2028.1 C2029.1 C2030.2 C2033.2 C2034.2 C2037.1 C2038.1 C2039.1 C2040.1 C2041.1 C2042.1 D1.1 D2.2 D3.2 D4.2 D5.2 D6.2 D7.2 D8.2 D9.2 D10.2 D11.2 D12.2 D13.3 D14.1 D15.1 D16.2 D19.1 D20.2 D21.2 D22.2 D27.2 D28.2 D29.2 D30.2 D31.2 D32.2 D33.2 D34.1 D35.2 D36.2 D37.2 D38.2 D39.2 D40.2 D41.2 D42.2 D43.2 D44.2 D45.2 D46.1 D47.2 D48.1 D49.1 D50.1 D51.1 D54.2 D55.2 D56.2 D57.2 D58.2 D59.1 D65.2 D66.1 D67.1 D68.2 D69.2 D70.1 D71.2 D72.2 D73.2 D74.2 FB3.2 FB10.2 FB11.2 FB15.1 FB21.2 FB22.2 FB23.2 FB24.2 FB28.1 FB33.2 FV1.1 FV2.1 J1.6 J2.6 J2.10 J2.11 J3.A2 J3.A8 J3.A9 J3.A10 J3.A11 J3.B3 J3.B10 J4.3 J4.8 J4.9 J4.10 J4.11 J5.A7 J5.A10 J5.A11 J5.B6 J5.B7 J5.B10 J5.B11 J6.A2 J6.A4 J6.A9 J6.A10 J6.A11 J6.B9 J6.B10 J6.B11 J7.2 J8.A6 J8.A7 J8.A10 J8.A11 J8.B9 J8.B10 J8.B11 J9.6 J9.9 J9.10 J9.11 J10.6 J10.13 J10.14 J11.6 J12.6 J12.7 J12.8 J12.9 J12.10 J12.11 pad. Q1.2 Q2.2 Q3.2 Q4.2 Q5.2 Q6.2 Q7.2 Q8.2 Q9.2 Q10.2 Q11.2 Q12.2 Q13.2 Q14.2 Q15.2 R8.1 R10.1 R21.1 R54.1 R55.1 R80.1 R83.1 R84.1 R85.1 R86.1 R87.1 R88.1 R101.2 R109.1 R110.1 R145.1 R146.1 R154.1 R157.1 R158.1 R163.1 R164.1 R181.1 R195.1 R200.1 R202.1 R203.1 R205.2 R225.1 R262.2 R282.1 R285.1 R286.1 R287.1 R288.1 R289.1 R290.1 R291.2 R300.2 R301.2 R305.1 R313.2 R315.1 R316.1 R319.1 R320.1 R342.1 R343.1 R346.1 R347.1 R348.1 R349.1 R1032.1 R1039.1 R2002.2 R2009.1 R2010.1 R2011.1 R2016.1 R2018.1 R2021.1 R2027.1 R2031.1 R2032.1 R2033.1 R2037.1 R2039.1 R2049.1 R2050.1 R2051.1 R2053.1 R2056.1 RJ1.13 RJ1.14 RJ2.13 RJ2.14 RJ3.6 RJ3.13 RJ3.14 U1.1 U1.2 U1.3 U1.4 U1.7 U2.10 U2.19 U2.20 U2.27 U2.49 U2.74 U2.99 U3.8 U3.10 U3.15 U6.1 U6.4 U7.4 U8.4 U9.3 U9.9 U9.14 U9.16 U9.19 U9.29 U9.48 U10.25 U10.35 U11.4 U12.4 U14.4 U16.16 U16.31 U16.38 U16.51 U16.61 U16.83 U16.94 U16.107 U16.120 U16.130 U17.25 U17.35 U18.3 U18.6 U19.4 U20.1 U21.3 U23.7 U24.4 U24.5 U24.6 U24.7 U24.8 U24.9 U25.4 U26.3 U27.1 U34.3 U34.6 U36.4 U37.3 U37.9 U37.14 U37.16 U37.19 U37.29 U37.48 U38.2 U39.9 U39.11 U39.13 U39.15 U40.2 U40.9 U40.11 U40.15 U41.4 U42.4 U43.4 U1007.4 U2001.5 U2001.17 U2002.4 U2003.5 U2003.17 U2004.4 U2005.5 U2005.17 U2006.4 X3.2 | length 136.2
  Top Layer w0.191: v1(54.5,-169.25) 54.561,-169.189 54.975,-169.189 55.164,-169 v1(55.25,-169)
  Top Layer w0.203: v1(43.256,1.905) 43.698,1.463 U9.9@45.092,1.463 ; v1(43.282,4.115) 43.63,4.463 U9.3@45.092,4.463 ; v1(46.28,7.213) 46.315,7.213 46.323,7.221 46.33,7.213 U9.48@46.842,7.213 ; 47.342,-3.48 U9.14@47.342,-1.787 ; v1(47.872,-3.498) v1@47.974,-3.498 ; 48.342,-25.699 U37.16@48.342,-24.025 ; 48.342,-3.363 U9.16@48.342,-1.787 ; U37.19@49.842,-24.025 49.842,-22.352 ; 49.842,-0.196 U9.19@49.842,-1.787 U9.19@49.853,-1.775 ; v1(52.52,1.963) U9.29@54.092,1.963 ; v1(52.657,-20.287) 52.669,-20.275 U37.29@54.092,-20.275
  Top Layer w0.254: U2001.5@26.169,-169.369 U2001.17@26.169,-168.519 ; U2005.5@26.257,-199.724 U2005.17@26.257,-198.874 ; U2003.5@26.257,-184.484 U2003.17@26.257,-183.634 ; v1(43.287,-20.229) 43.834,-20.775 U37.9@45.092,-20.775 ; v1(43.44,-17.994) 43.658,-17.775 U37.3@45.092,-17.775 ; 47.342,-25.534 U37.14@47.342,-24.025 ; U16.107@72.801,-93.237 74.669,-93.237 74.931,-93.5 v1(75,-93.5) ; U16.94@72.801,-86.737 75.237,-86.737 75.25,-86.75 ; U16.83@72.801,-81.237 75.237,-81.237 75.25,-81.25 ; 72.954,-196.503 U17.25@72.954,-196.059 73.628,-196.059 73.774,-196.205 v1(73.774,-197.094) ; U17.35@72.954,-191.059 74.343,-191.059 v1(74.511,-191.226) ; 73.094,-169.053 U10.25@73.094,-168.609 73.768,-168.609 73.914,-168.755 v1(73.914,-169.644) ; U10.35@73.094,-163.609 74.483,-163.609 v1(74.651,-163.776) ; v1(80.5,-76) 80.5,-75.931 80.551,-75.881 U16.61@80.551,-73.987 ; U16.120@80.551,-95.987 80.568,-95.97 80.568,-94.716 81,-94.283 v1(81,-94.25) ; v1(85.534,-75.716) 85.534,-74.004 U16.51@85.551,-73.987 ; U16.130@85.551,-95.987 85.568,-95.97 85.568,-94.716 86,-94.283 v1(86,-94.25) ; v1(91.75,-75.75) 91.75,-75.681 92.034,-75.398 92.034,-74.004 U16.38@92.051,-73.987 ; v1(93,-78.75) 93.006,-78.744 94.794,-78.744 U16.31@94.801,-78.737 ; v1(93.037,-86.254) 93.045,-86.246 94.792,-86.246 U16.16@94.801,-86.237 ; U2.49@93.096,-189.281 95.281,-189.281 95.5,-189.5 ; U2.27@93.096,-178.281 93.112,-178.266 95.234,-178.266 v1(95.25,-178.25) ; v1(97.25,-177.75) 97.259,-177.75 97.596,-177.412 U2.20@97.596,-175.781 ; v1(97.75,-177.75) 97.759,-177.75 98.096,-177.412 U2.19@98.096,-175.781 ; v1(102,-177.75) 102.596,-177.154 U2.10@102.596,-175.781 ; v1(106.5,-190) 106.5,-190.069 106.596,-190.165 U2.74@106.596,-191.781 ; U2.99@109.096,-178.281 109.112,-178.266 111.234,-178.266 v1(111.25,-178.25)
  Top Layer w0.305: 25.75,-171.25 26.169,-170.831 U2001.5@26.169,-169.369 ; 26.25,-186 26.257,-185.993 U2003.5@26.257,-184.484 ; 26.257,-201.493 U2005.5@26.257,-199.724
  Top Layer w0.381: v1@37.581,-200.19 R2053.1@38.194,-200.19 ; v1@37.607,-184.93 R2027.1@38.219,-184.93 ; v1@37.632,-169.845 R2016.1@38.245,-169.845 ; v1(82,-112.25) 82,-112.216 81.953,-112.169 81.953,-111.297 U19.4@81.948,-111.292 81.948,-110.302 82.5,-109.75
  Top Layer w0.406: 46.74,-16.612 U37.48@46.74,-14.416
  Top Layer w0.508: J5.B10@12.006,-46.846 12.006,-47.5 v1(18.25,-47.5) v1(19.5,-47.5) D44.2@20.35,-47.5 ; v1(18.5,-45.5) v2(19.5,-45.5) D45.2@20.35,-45.5 ; v1(18.5,-43.75) v2(19.5,-43.75) D43.2@20.35,-43.75 ; v2(18.5,-42) v2(19.5,-42) D5.2@20.35,-42 ; v1(18.5,-40.25) D47.2@20.35,-40.25 ; v2(18.5,-38.5) v2(19.5,-38.5) D4.2@20.35,-38.5 ; v2(18.5,-36.75) v2(19.5,-36.75) D10.2@20.35,-36.75 ; v2(18.5,-35) v2(19.5,-35) D9.2@20.35,-35 ; v2(18.5,-32.75) v2(19.5,-32.75) D8.2@20.35,-32.75 ; v2(18.5,-31) v2(19.5,-31) D7.2@20.35,-31 ; v2(18.5,-29.25) v2(19.5,-29.25) D3.2@20.35,-29.25 ; v2(18.5,-27.5) D2.2@20.35,-27.5 ; D39.2@19.1,-74.5 v1(19.75,-74.5) ; D40.2@19.1,-72.5 v1(19.75,-72.5) ; D38.2@19.1,-70.5 v1(19.75,-70.5) ; v2(20,-127.5) D22.2@20.85,-127.5 ; v2(20,-125.5) D20.2@20.85,-125.5 ; C2002.2@27.998,-163.613 C2001.1@27.998,-162.309 ; C2030.2@28.074,-194.145 v1(28.074,-193.546) C2029.1@28.074,-192.841 ; C2016.2@28.074,-178.905 v1(28.074,-178.306) C2015.1@28.074,-177.601 ; v1(47.5,-142.25) Q15.2@48.25,-142.25 ; FB33.2@48,-147.75 v1(48,-147) ; R349.1@50.25,-142.4 50.35,-142.5 v1(51.25,-142.5) ; C46.1@53.105,-4.895 v1(53.105,-4.088) ; C43.1@57.905,-4.858 v1(58.712,-4.858) ; 58.375,-58.25 57.896,-57.771 57.178,-57.771 U38.2@57.157,-57.75 v2(58.007,-57.75) 59.375,-57.75 ; v1(59.689,0.097) C42.1@60.496,0.097 ; C238.1@60.496,-16.905 v1(60.496,-16.098) ; C44.1@60.503,5.029 v1(60.503,5.836) ; U34.3@113.75,-17.5 113.75,-17.675 114.354,-18.279 114.354,-19.204 C95.1@114.65,-19.5 ; v1(115.824,-136.144) U40.11@115.824,-134.874 ; v1(120.904,-136.119) U40.15@120.904,-134.874 ; U18.3@124.75,-16.85 124.75,-17.675 125.5,-18.425 v1(125.5,-18.5) C132.1@125.5,-19 ; D32.2@130.69,-136.398 v1(131.191,-136.398) ; D33.2@130.69,-134.366 v1(131.191,-134.366)
  Bottom Layer w0.508: D28.2@130.69,-140.462 v1(131.191,-140.462) ; D29.2@130.69,-138.43 v1(131.191,-138.43)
